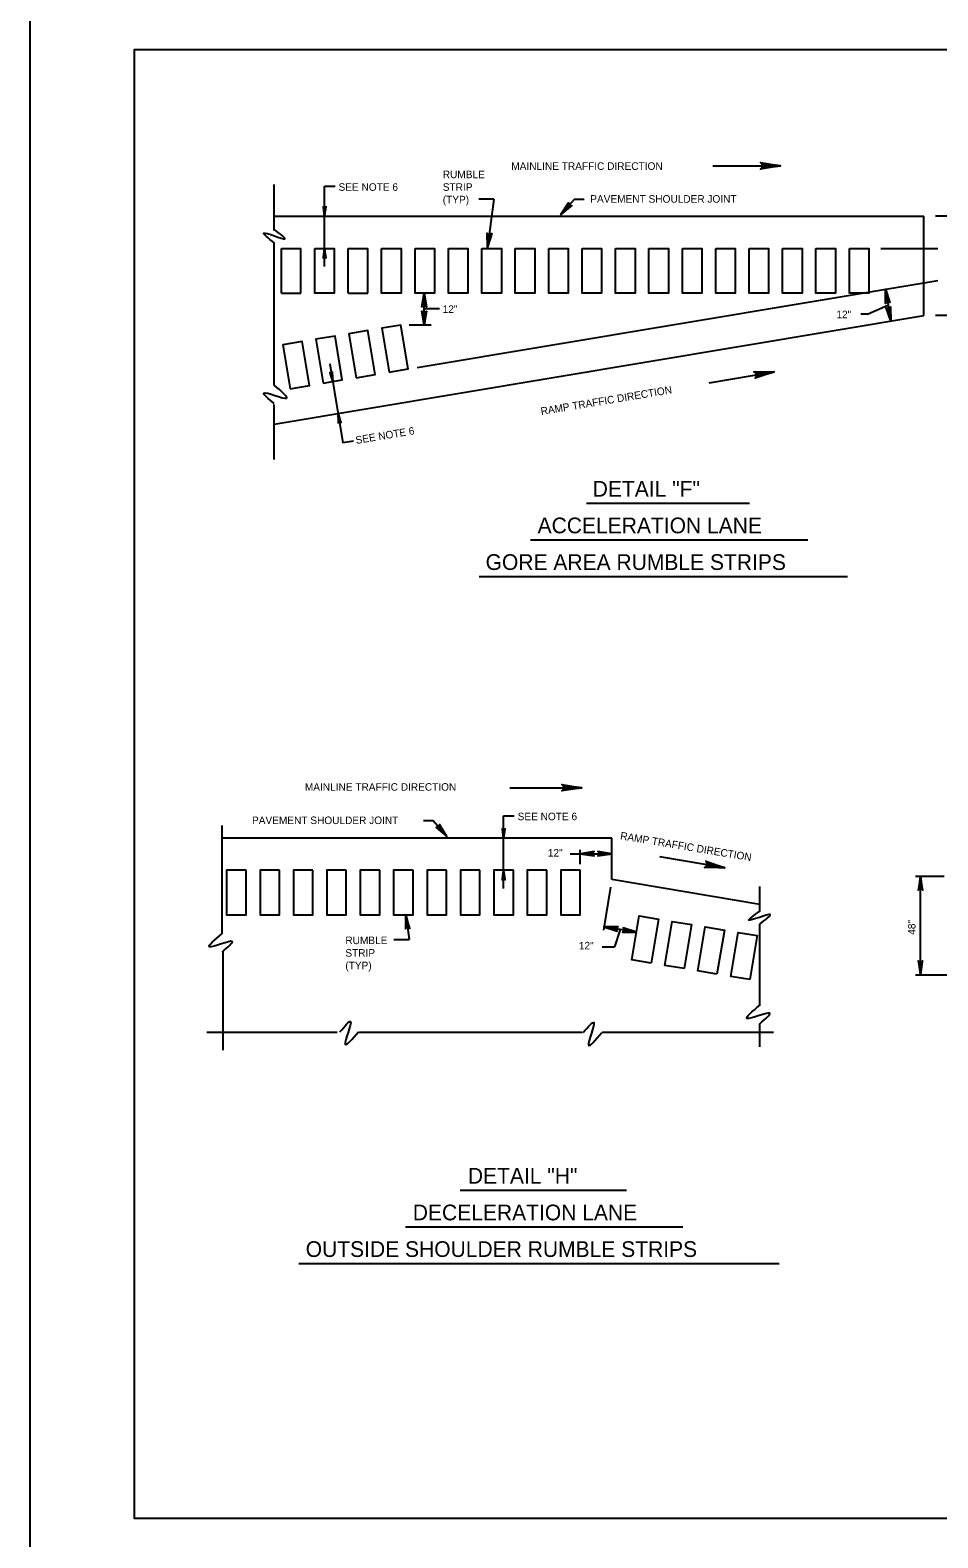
# Model space of a CAD drawing. Extents: x 632008 to 634206, y 294231 to 297795.
# Drawn here: x 632008 to 632356, y 294832 to 295411 of the extents above; entities that cross this region are included whole.
import ezdxf

# ---------------------------------------------------------------- set-up
doc = ezdxf.new("R2010")
doc.units = 0
doc.layers.add('1', color=7, linetype='Continuous')
doc.layers.add('PLT-BNDY', color=7, linetype='Continuous')

msp = doc.modelspace()

# ---------------------------------------------------------------- linework, layer by layer
at = {"layer": '1'}
for p, q in [((632270, 295359.01), (632296.09, 295359.01)), ((632101.52, 295334.17), (632101.52, 295351.91)), ((632120.92, 295320.33), (632120.92, 295351.15)), ((632120.92, 295351.15), (632124.96, 295351.15)), ((632185.99, 295346.16), (632180.14, 295346.16)), ((632185.99, 295346.16), (632183.57, 295327.82)), ((632101.52, 295339.67), (632351.06, 295339.67)), ((632351.06, 295301.54), (632351.06, 295339.67)), ((632365.52, 295339.67), (632355.54, 295339.67)), ((632101.52, 295274.82), (632101.52, 295329.59)), ((632104.35, 295310.18), (632104.35, 295327.29)), ((632104.35, 295327.29), (632111.83, 295327.29)), ((632111.83, 295310.18), (632111.83, 295327.29)), ((632130.01, 295310.18), (632130.01, 295327.29)), ((632130.01, 295327.29), (632137.5, 295327.29)), ((632137.5, 295310.18), (632137.5, 295327.29)), ((632334.53, 295327.29), (632356.44, 295327.29)), ((632156.51, 295281.58), (632356.44, 295314.97)), ((632104.35, 295310.18), (632111.83, 295310.18)), ((632130.01, 295310.18), (632137.5, 295310.18)), ((632159.19, 295297.89), (632159.19, 295310.18)), ((632336.33, 295311.62), (632338.37, 295299.42)), ((632165.04, 295304.09), (632159.19, 295304.09)), ((632329.71, 295302.05), (632326.94, 295302.05)), ((632337.3, 295305.43), (632329.71, 295302.05)), ((632101.52, 295259.86), (632351.06, 295301.54)), ((632161.82, 295297.89), (632153.45, 295297.89)), ((632365.52, 295301.54), (632355.54, 295301.54)), ((632122.93, 295283.03), (632128, 295252.64)), ((632268.61, 295275.73), (632293.64, 295279.91)), ((632101.52, 295246.18), (632101.52, 295267.37)), ((632131.99, 295253.31), (632128, 295252.64)), ((632221.58, 295229.51), (632284.08, 295229.51)), ((632200.01, 295215.38), (632306.52, 295215.38)), ((632180.29, 295201.26), (632321.8, 295201.26)), ((632192.12, 295120.19), (632218.22, 295120.19)), ((632081.55, 295064.1), (632081.55, 295105.68)), ((632189.71, 295081.51), (632189.71, 295109.42)), ((632189.71, 295109.42), (632193.76, 295109.42)), ((632231.27, 295100.85), (632081.55, 295100.85)), ((632231.27, 295084.89), (632231.27, 295100.85)), ((632215.32, 295094.85), (632231.27, 295094.85)), ((632219.12, 295090.82), (632219.12, 295096.38)), ((632274.69, 295089.46), (632249.67, 295093.64)), ((632230.79, 295082.04), (632228.02, 295065.45)), ((632288.1, 295075.4), (632231.27, 295084.89)), ((632288.1, 295072.72), (632288.1, 295082.23)), ((632347.86, 295086.17), (632358.85, 295086.17)), ((632349.8, 295048.39), (632349.8, 295086.17)), ((632152.18, 295071.37), (632153.43, 295061.89)), ((632240.72, 295064.68), (632228.24, 295066.76)), ((632234.42, 295065.73), (632232.27, 295059.15)), ((632288.1, 295036.46), (632288.1, 295067.8)), ((632147.58, 295061.89), (632153.43, 295061.89)), ((632227.6, 295059.15), (632232.27, 295059.15)), ((632081.93, 295019.37), (632081.93, 295057.49)), ((632347.86, 295048.39), (632360.69, 295048.39)), ((632288.1, 295020.66), (632288.1, 295029.53)), ((632125.75, 295026.19), (632075.73, 295026.19)), ((632219.83, 295026.19), (632134.13, 295026.19)), ((632293.37, 295026.19), (632227.56, 295026.19)), ((632173.04, 294965.67), (632236.93, 294965.67)), ((632152.06, 294951.54), (632258.58, 294951.54)), ((632111.08, 294937.42), (632295.5, 294937.42))]:
    msp.add_line(p, q, dxfattribs=at)
for points in [[(632833.86, 294839.62), (632833.86, 295403.62), (632047.86, 295403.62), (632047.86, 294839.62), (632833.86, 294839.62), (632833.86, 294865.98), (632633.86, 294865.98), (632633.86, 294930.66), (632833.86, 294930.66), (632833.86, 294959.62), (632633.86, 294959.62), (632633.86, 294839.62), (632712.66, 294839.62), (632712.66, 294865.98), (632712.66, 294839.62), (632789.66, 294839.62), (632789.66, 294865.98), (632789.66, 294853.66), (632833.86, 294853.66)], [(632833.86, 294839.62), (632833.86, 295403.62), (632047.86, 295403.62), (632047.86, 294839.62), (632833.86, 294839.62), (632833.86, 294865.98), (632633.86, 294865.98), (632633.86, 294930.66), (632833.86, 294930.66), (632833.86, 294959.62), (632633.86, 294959.62), (632633.86, 294839.62), (632712.66, 294839.62), (632712.66, 294865.98), (632712.66, 294839.62), (632789.66, 294839.62), (632789.66, 294865.98), (632789.66, 294853.66), (632833.86, 294853.66)], [(632833.86, 294839.62), (632833.86, 295403.62), (632047.86, 295403.62), (632047.86, 294839.62), (632833.86, 294839.62), (632833.86, 294865.98), (632633.86, 294865.98), (632633.86, 294930.66), (632833.86, 294930.66), (632833.86, 294959.62), (632633.86, 294959.62), (632633.86, 294839.62), (632712.66, 294839.62), (632712.66, 294865.98), (632712.66, 294839.62), (632789.66, 294839.62), (632789.66, 294865.98), (632789.66, 294853.66), (632833.86, 294853.66)], [(632833.86, 294839.62), (632833.86, 295403.62), (632047.86, 295403.62), (632047.86, 294839.62), (632833.86, 294839.62), (632833.86, 294865.98), (632633.86, 294865.98), (632633.86, 294930.66), (632833.86, 294930.66), (632833.86, 294959.62), (632633.86, 294959.62), (632633.86, 294839.62), (632712.66, 294839.62), (632712.66, 294865.98), (632712.66, 294839.62), (632789.66, 294839.62), (632789.66, 294865.98), (632789.66, 294853.66), (632833.86, 294853.66)], [(632833.86, 294839.62), (632833.86, 295403.62), (632047.86, 295403.62), (632047.86, 294839.62), (632833.86, 294839.62), (632833.86, 294865.98), (632633.86, 294865.98), (632633.86, 294930.66), (632833.86, 294930.66), (632833.86, 294959.62), (632633.86, 294959.62), (632633.86, 294839.62), (632712.66, 294839.62), (632712.66, 294865.98), (632712.66, 294839.62), (632789.66, 294839.62), (632789.66, 294865.98), (632789.66, 294853.66), (632833.86, 294853.66)], [(632833.86, 294839.62), (632833.86, 295403.62), (632047.86, 295403.62), (632047.86, 294839.62), (632833.86, 294839.62), (632833.86, 294865.98), (632633.86, 294865.98), (632633.86, 294930.66), (632833.86, 294930.66), (632833.86, 294959.62), (632633.86, 294959.62), (632633.86, 294839.62), (632712.66, 294839.62), (632712.66, 294865.98), (632712.66, 294839.62), (632789.66, 294839.62), (632789.66, 294865.98), (632789.66, 294853.66), (632833.86, 294853.66)], [(632288.78, 295359.93), (632289.06, 295359.4), (632296.09, 295359.01), (632288.78, 295359.93), (632288.41, 295360.25), (632296.09, 295359.01), (632289.06, 295358.66), (632288.81, 295358.14), (632296.09, 295359.01), (632288.41, 295357.79), (632288.81, 295358.14)], [(632120.49, 295343.1), (632120.74, 295342.97), (632120.92, 295339.67), (632120.49, 295343.1), (632120.34, 295343.27), (632120.92, 295339.67), (632121.09, 295342.96), (632121.33, 295343.08), (632120.92, 295339.67), (632121.5, 295343.27), (632121.33, 295343.08)], [(632211.68, 295340.31), (632216.94, 295346.27), (632220.68, 295346.27)], [(632215.52, 295343.69), (632215.11, 295343.79), (632211.68, 295340.31), (632215.52, 295343.69), (632215.85, 295343.74), (632211.68, 295340.31), (632214.73, 295344.13), (632214.57, 295344.5), (632211.68, 295340.31), (632214.57, 295344.87), (632214.57, 295344.5)], [(632184.86, 295332.76), (632184.48, 295332.63), (632183.57, 295327.82), (632184.86, 295332.76), (632185.12, 295332.99), (632183.57, 295327.82), (632183.97, 295332.69), (632183.63, 295332.91), (632183.57, 295327.82), (632183.43, 295333.22), (632183.63, 295332.91)], [(632117.18, 295327.29), (632124.67, 295327.29), (632124.67, 295310.18), (632117.18, 295310.18), (632117.18, 295327.29)], [(632121.35, 295323.87), (632121.11, 295323.99), (632120.92, 295327.29), (632121.35, 295323.87), (632121.5, 295323.69), (632120.92, 295327.29), (632120.76, 295324), (632120.51, 295323.88), (632120.92, 295327.29), (632120.35, 295323.69), (632120.51, 295323.88)], [(632142.85, 295327.29), (632150.33, 295327.29), (632150.33, 295310.18), (632142.85, 295310.18), (632142.85, 295327.29)], [(632155.68, 295327.29), (632163.17, 295327.29), (632163.17, 295310.18), (632155.68, 295310.18), (632155.68, 295327.29)], [(632168.51, 295327.29), (632176, 295327.29), (632176, 295310.18), (632168.51, 295310.18), (632168.51, 295327.29)], [(632181.35, 295327.29), (632188.83, 295327.29), (632188.83, 295310.18), (632181.35, 295310.18), (632181.35, 295327.29)], [(632194.18, 295327.29), (632201.67, 295327.29), (632201.67, 295310.18), (632194.18, 295310.18), (632194.18, 295327.29)], [(632207.01, 295327.29), (632214.5, 295327.29), (632214.5, 295310.18), (632207.01, 295310.18), (632207.01, 295327.29)], [(632219.85, 295327.29), (632227.33, 295327.29), (632227.33, 295310.18), (632219.85, 295310.18), (632219.85, 295327.29)], [(632232.68, 295327.29), (632240.17, 295327.29), (632240.17, 295310.18), (632232.68, 295310.18), (632232.68, 295327.29)], [(632245.52, 295327.29), (632253, 295327.29), (632253, 295310.18), (632245.52, 295310.18), (632245.52, 295327.29)], [(632258.35, 295327.29), (632265.83, 295327.29), (632265.83, 295310.18), (632258.35, 295310.18), (632258.35, 295327.29)], [(632271.18, 295327.29), (632278.67, 295327.29), (632278.67, 295310.18), (632271.18, 295310.18), (632271.18, 295327.29)], [(632284.02, 295327.29), (632291.5, 295327.29), (632291.5, 295310.18), (632284.02, 295310.18), (632284.02, 295327.29)], [(632296.85, 295327.29), (632304.34, 295327.29), (632304.34, 295310.18), (632296.85, 295310.18), (632296.85, 295327.29)], [(632309.68, 295327.29), (632317.17, 295327.29), (632317.17, 295310.18), (632309.68, 295310.18), (632309.68, 295327.29)], [(632322.52, 295327.29), (632330, 295327.29), (632330, 295310.18), (632322.52, 295310.18), (632322.52, 295327.29)], [(632158.56, 295305.11), (632158.92, 295305.3), (632159.19, 295310.18), (632158.56, 295305.11), (632158.33, 295304.85), (632159.19, 295310.18), (632159.44, 295305.3), (632159.8, 295305.12), (632159.19, 295310.18), (632160.04, 295304.85), (632159.8, 295305.12)], [(632336.54, 295306.51), (632336.87, 295306.75), (632336.33, 295311.62), (632336.54, 295306.51), (632336.36, 295306.21), (632336.33, 295311.62), (632337.38, 295306.84), (632337.76, 295306.73), (632336.33, 295311.62), (632338.05, 295306.5), (632337.76, 295306.73)], [(632159.83, 295302.96), (632159.46, 295302.77), (632159.19, 295297.89), (632159.83, 295302.96), (632160.05, 295303.22), (632159.19, 295297.89), (632158.95, 295302.77), (632158.59, 295302.95), (632159.19, 295297.89), (632158.35, 295303.22), (632158.59, 295302.95)], [(632338.16, 295304.53), (632337.83, 295304.28), (632338.37, 295299.42), (632338.16, 295304.53), (632338.34, 295304.82), (632338.37, 295299.42), (632337.33, 295304.19), (632336.94, 295304.31), (632338.37, 295299.42), (632336.66, 295304.54), (632336.94, 295304.31)], [(632145.7, 295279.78), (632153.08, 295281.01), (632150.26, 295297.89), (632142.88, 295296.65), (632145.7, 295279.78)], [(632107.72, 295273.43), (632115.11, 295274.67), (632112.29, 295291.55), (632104.9, 295290.31), (632107.72, 295273.43)], [(632120.38, 295275.55), (632127.76, 295276.78), (632124.95, 295293.66), (632117.56, 295292.43), (632120.38, 295275.55)], [(632133.04, 295277.66), (632140.42, 295278.9), (632137.6, 295295.77), (632130.22, 295294.54), (632133.04, 295277.66)], [(632123.08, 295279.48), (632123.35, 295279.39), (632124.07, 295276.17), (632123.08, 295279.48), (632122.91, 295279.62), (632124.07, 295276.17), (632123.69, 295279.44), (632123.91, 295279.6), (632124.07, 295276.17), (632124.04, 295279.81), (632123.91, 295279.6)], [(632286.28, 295279.61), (632286.64, 295279.14), (632293.64, 295279.91), (632286.28, 295279.61), (632285.86, 295279.87), (632293.64, 295279.91), (632286.76, 295278.41), (632286.6, 295277.85), (632293.64, 295279.91), (632286.26, 295277.44), (632286.6, 295277.85)], [(632127.1, 295260.65), (632126.84, 295260.74), (632126.11, 295263.96), (632127.1, 295260.65), (632127.28, 295260.5), (632126.11, 295263.96), (632126.49, 295260.68), (632126.27, 295260.52), (632126.11, 295263.96), (632126.14, 295260.31), (632126.27, 295260.52)], [(632212.44, 295121.11), (632212.71, 295120.58), (632219.75, 295120.19), (632212.44, 295121.11), (632212.07, 295121.43), (632219.75, 295120.19), (632212.72, 295119.85), (632212.46, 295119.32), (632219.75, 295120.19), (632212.07, 295118.97), (632212.46, 295119.32)], [(632167.96, 295101.49), (632162.7, 295107.45), (632158.96, 295107.45)], [(632164.12, 295104.88), (632164.52, 295104.98), (632167.96, 295101.49), (632164.12, 295104.88), (632163.78, 295104.92), (632167.96, 295101.49), (632164.91, 295105.31), (632165.06, 295105.69), (632167.96, 295101.49), (632165.06, 295106.05), (632165.06, 295105.69)], [(632189.28, 295104.28), (632189.53, 295104.15), (632189.71, 295100.85), (632189.28, 295104.28), (632189.13, 295104.45), (632189.71, 295100.85), (632189.88, 295104.15), (632190.12, 295104.27), (632189.71, 295100.85), (632190.29, 295104.45), (632190.12, 295104.27)], [(632224.2, 295095.49), (632224.01, 295095.12), (632219.12, 295094.85), (632224.2, 295095.49), (632224.46, 295095.71), (632219.12, 295094.85), (632224.01, 295094.61), (632224.18, 295094.25), (632219.12, 295094.85), (632224.46, 295094.01), (632224.18, 295094.25)], [(632226.19, 295094.22), (632226.38, 295094.58), (632231.27, 295094.85), (632226.19, 295094.22), (632225.93, 295093.99), (632231.27, 295094.85), (632226.38, 295095.1), (632226.21, 295095.46), (632231.27, 295094.85), (632225.93, 295095.7), (632226.21, 295095.46)], [(632090.79, 295088.48), (632083.3, 295088.48), (632083.3, 295071.37), (632090.79, 295071.37), (632090.79, 295088.48)], [(632103.62, 295088.48), (632096.14, 295088.48), (632096.14, 295071.37), (632103.62, 295071.37), (632103.62, 295088.48)], [(632116.46, 295088.48), (632108.97, 295088.48), (632108.97, 295071.37), (632116.46, 295071.37), (632116.46, 295088.48)], [(632129.29, 295088.48), (632121.8, 295088.48), (632121.8, 295071.37), (632129.29, 295071.37), (632129.29, 295088.48)], [(632142.12, 295088.48), (632134.64, 295088.48), (632134.64, 295071.37), (632142.12, 295071.37), (632142.12, 295088.48)], [(632154.96, 295088.48), (632147.47, 295088.48), (632147.47, 295071.37), (632154.96, 295071.37), (632154.96, 295088.48)], [(632167.79, 295088.48), (632160.3, 295088.48), (632160.3, 295071.37), (632167.79, 295071.37), (632167.79, 295088.48)], [(632180.62, 295088.48), (632173.14, 295088.48), (632173.14, 295071.37), (632180.62, 295071.37), (632180.62, 295088.48)], [(632193.46, 295088.48), (632185.97, 295088.48), (632185.97, 295071.37), (632193.46, 295071.37), (632193.46, 295088.48)], [(632190.14, 295085.05), (632189.9, 295085.18), (632189.71, 295088.48), (632190.14, 295085.05), (632190.3, 295084.88), (632189.71, 295088.48), (632189.55, 295085.18), (632189.31, 295085.06), (632189.71, 295088.48), (632189.14, 295084.88), (632189.31, 295085.06)], [(632206.29, 295088.48), (632198.8, 295088.48), (632198.8, 295071.37), (632206.29, 295071.37), (632206.29, 295088.48)], [(632219.12, 295088.48), (632211.64, 295088.48), (632211.64, 295071.37), (632219.12, 295071.37), (632219.12, 295088.48)], [(632267.64, 295091.57), (632267.82, 295091), (632274.69, 295089.46), (632267.64, 295091.57), (632267.32, 295091.95), (632274.69, 295089.46), (632267.7, 295090.28), (632267.36, 295089.8), (632274.69, 295089.46), (632266.91, 295089.52), (632267.36, 295089.8)], [(632350.44, 295081.1), (632350.07, 295081.29), (632349.8, 295086.17), (632350.44, 295081.1), (632350.66, 295080.84), (632349.8, 295086.17), (632349.56, 295081.29), (632349.2, 295081.11), (632349.8, 295086.17), (632348.96, 295080.84), (632349.2, 295081.11)], [(632153.48, 295066.42), (632153.09, 295066.56), (632152.18, 295071.37), (632153.48, 295066.42), (632153.73, 295066.19), (632152.18, 295071.37), (632152.58, 295066.5), (632152.24, 295066.27), (632152.18, 295071.37), (632152.04, 295065.97), (632152.24, 295066.27)], [(632246.34, 295052.86), (632238.96, 295054.1), (632241.78, 295070.97), (632249.16, 295069.74), (632246.34, 295052.86)], [(632233.35, 295066.55), (632233.1, 295066.22), (632228.24, 295066.76), (632233.35, 295066.55), (632233.64, 295066.73), (632228.24, 295066.76), (632233.01, 295065.72), (632233.13, 295065.33), (632228.24, 295066.76), (632233.36, 295065.05), (632233.13, 295065.33)], [(632235.61, 295064.88), (632235.86, 295065.22), (632240.72, 295064.68), (632235.61, 295064.88), (632235.32, 295064.71), (632240.72, 295064.68), (632235.95, 295065.72), (632235.83, 295066.11), (632240.72, 295064.68), (632235.6, 295066.39), (632235.83, 295066.11)], [(632259, 295050.75), (632251.61, 295051.98), (632254.43, 295068.86), (632261.82, 295067.63), (632259, 295050.75)], [(632271.66, 295048.63), (632264.27, 295049.87), (632267.09, 295066.74), (632274.48, 295065.51), (632271.66, 295048.63)], [(632284.31, 295046.52), (632276.93, 295047.75), (632279.75, 295064.63), (632287.13, 295063.4), (632284.31, 295046.52)], [(632349.17, 295053.46), (632349.53, 295053.28), (632349.8, 295048.39), (632349.17, 295053.46), (632348.94, 295053.72), (632349.8, 295048.39), (632350.04, 295053.27), (632350.41, 295053.45), (632349.8, 295048.39), (632350.65, 295053.72), (632350.41, 295053.45)]]:
    msp.add_lwpolyline(points, dxfattribs=at)
for points in [[(632101.58, 295329.45), (632097.58, 295333.21), (632105.69, 295330.98), (632101.58, 295334.51)], [(632101.56, 295267.71), (632097.64, 295271.77), (632106.34, 295269.74), (632101.56, 295274.82)], [(632288.05, 295067.75), (632292.04, 295071.51), (632283.94, 295069.28), (632288.05, 295072.8)], [(632081.58, 295057.1), (632085.49, 295061.16), (632076.79, 295059.13), (632081.58, 295064.21)], [(632288.07, 295029.54), (632291.98, 295033.6), (632283.28, 295031.57), (632288.07, 295036.65)], [(632126.84, 295026.47), (632130.9, 295030.38), (632128.87, 295021.68), (632133.95, 295026.47)], [(632220.27, 295026.15), (632224.33, 295030.06), (632222.3, 295021.36), (632227.38, 295026.15)]]:
    msp.add_spline(points, degree=3, dxfattribs=at)
at = {"layer": 'PLT-BNDY'}
msp.add_lwpolyline([(632007.86, 295418.62), (632848.86, 295418.62), (632848.86, 294824.62), (632007.86, 294824.62)], close=True, dxfattribs=at)

# ---------------------------------------------------------------- texts
at = {"layer": '1'}
for s, height, p in [('MAINLINE TRAFFIC DIRECTION', 2.8989, (632192.65, 295357.47)), ('RUMBLE', 2.899, (632166.33, 295354.26)), ('SEE NOTE 6', 2.899, (632126.3, 295349.43)), ('STRIP', 2.899, (632166.33, 295349.43)), ('(TYP)', 2.899, (632166.33, 295344.6)), ('PAVEMENT SHOULDER JOINT', 2.898, (632222.99, 295344.86)), ('12"', 2.899, (632166.29, 295302.52)), ('12"', 2.899, (632317.52, 295300.5)), ('DETAIL "F"', 6.039, (632223.93, 295231.97)), ('ACCELERATION LANE', 6.0395, (632202.76, 295217.9)), ('GORE AREA RUMBLE STRIPS', 6.0395, (632182.79, 295203.82)), ('MAINLINE TRAFFIC DIRECTION', 2.8989, (632113.37, 295119.04)), ('SEE NOTE 6', 2.899, (632195.09, 295107.71)), ('PAVEMENT SHOULDER JOINT', 2.898, (632093.07, 295106.23)), ('12"', 2.899, (632206.69, 295093.73)), ('RUMBLE', 2.899, (632128.92, 295060.14)), ('12"', 2.899, (632218.6, 295058.11)), ('STRIP', 2.899, (632128.92, 295055.31)), ('(TYP)', 2.899, (632128.92, 295050.48)), ('DETAIL "H"', 6.039, (632175.98, 294968.14)), ('DECELERATION LANE', 6.0395, (632154.82, 294954.06)), ('OUTSIDE SHOULDER RUMBLE STRIPS', 6.0395, (632113.7, 294939.99))]:
    msp.add_text(s, height=height, dxfattribs=at).set_placement(p)
for s, height, rotation, p in [('RAMP TRAFFIC DIRECTION', 2.8989, 9.48202, (632204.19, 295263.29)), ('SEE NOTE 6', 2.899, 9.48203, (632133.11, 295252.19)), ('RAMP TRAFFIC DIRECTION', 2.8989, 350.51798, (632234.33, 295100.41)), ('48"', 2.899, 90, (632347.89, 295063.71))]:
    msp.add_text(s, height=height, rotation=rotation, dxfattribs=at).set_placement(p)

doc.saveas('drawing.dxf')
